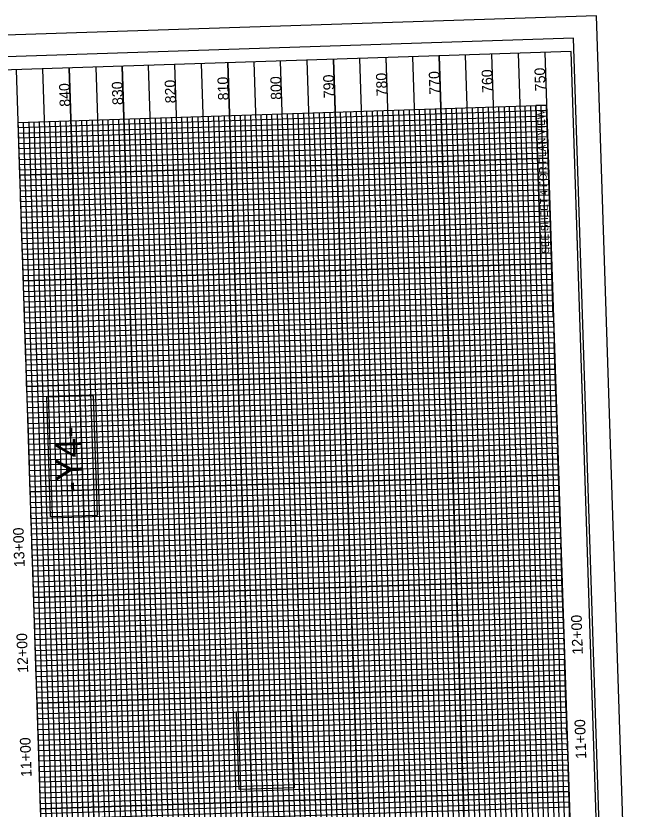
# Model space of a CAD drawing. Extents: x 1627314 to 1628469, y 762309 to 764230.
# Drawn here: x 1627864 to 1628469, y 763293 to 764044 of the extents above; entities that cross this region are included whole.
import ezdxf

# ---------------------------------------------------------------- set-up
doc = ezdxf.new("R2010")
doc.units = 0
for name, color, linetype in [('Exist Vertical Profile Horizontal Axis Label Major', 7, 'Continuous'), ('Exist Vertical Profile Vertical Axis Label', 7, 'Continuous'), ('Prop DSN Text', 7, 'Continuous'), ('Prop Grid Mask', 7, 'Continuous'), ('Sheet Data Field CELL', 7, 'Continuous'), ('Sheet DOT Grid CELL', 7, 'Continuous'), ('Sheet Layout Profile Border Port 2', 7, 'Continuous'), ('Sheet Plot Border Inside CELL', 7, 'Continuous'), ('Sheet Plot Border Outside CELL', 7, 'Continuous'), ('Sheet Profile CELL', 7, 'Continuous'), ('Sheet Profile Grid Major CELL', 7, 'Continuous'), ('Sheet Profile Grid Middle CELL', 7, 'Continuous'), ('Sheet Profile Grid Minor CELL', 7, 'Continuous')]:
    doc.layers.add(name, color=color, linetype=linetype)

msp = doc.modelspace()

# ---------------------------------------------------------------- linework, layer by layer
at = {"layer": 'Prop Grid Mask'}
for points in [[(1628356.37, 763959.45), (1628361.12, 763814.53), (1628371.11, 763814.85), (1628366.37, 763959.78)], [(1627941.73, 763571.76), (1627938.03, 763684.79), (1627893.31, 763683.33), (1627897.01, 763570.3)], [(1628075.63, 763311.97), (1628073.23, 763385.36), (1628125.26, 763387.06), (1628127.66, 763313.68)]]:
    msp.add_lwpolyline(points, close=True, dxfattribs=at)
at = {"layer": 'Sheet DOT Grid CELL'}
for p, q in [((1628313.83, 762507.28), (1628264.79, 764006.37)), ((1628363.8, 762508.92), (1628314.77, 764008)), ((1628063.96, 762499.11), (1628014.93, 763998.19)), ((1628113.93, 762500.74), (1628064.9, 763999.83)), ((1628163.91, 762502.38), (1628114.87, 764001.46)), ((1628213.88, 762504.01), (1628164.85, 764003.1)), ((1628263.85, 762505.65), (1628214.82, 764004.73)), ((1627914.04, 762494.2), (1627865.01, 763993.29)), ((1627964.01, 762495.84), (1627914.98, 763994.92)), ((1628013.99, 762497.47), (1627964.95, 763996.56)), ((1627866.64, 763943.43), (1628366.37, 763959.78)), ((1627868.27, 763893.46), (1628368, 763909.8)), ((1627869.91, 763843.48), (1628369.64, 763859.83)), ((1627871.54, 763793.51), (1628371.27, 763809.86)), ((1627873.18, 763743.54), (1628372.91, 763759.88)), ((1627874.81, 763693.56), (1628374.54, 763709.91)), ((1627876.44, 763643.59), (1628376.18, 763659.94)), ((1627878.08, 763593.62), (1628377.81, 763609.96)), ((1627879.71, 763543.64), (1628379.45, 763559.99)), ((1627881.35, 763493.67), (1628381.08, 763510.02)), ((1627882.98, 763443.7), (1628382.72, 763460.04)), ((1627884.62, 763393.72), (1628384.35, 763410.07)), ((1627886.25, 763343.75), (1628385.99, 763360.1)), ((1627887.89, 763293.78), (1628387.62, 763310.12))]:
    msp.add_line(p, q, dxfattribs=at)
at = {"layer": 'Sheet Layout Profile Border Port 2'}
msp.add_lwpolyline([(1627912.41, 762544.18), (1627866.64, 763943.43), (1628366.37, 763959.78), (1628412.14, 762560.52)], close=True, dxfattribs=at)
at = {"layer": 'Sheet Plot Border Inside CELL'}
msp.add_lwpolyline([(1628446.34, 762357.53), (1628391.86, 764023.14), (1627337.33, 763988.65), (1627391.81, 762323.04)], close=True, dxfattribs=at)
at = {"layer": 'Sheet Plot Border Outside CELL'}
msp.add_lwpolyline([(1628469.21, 762345.27), (1628413.63, 764044.37), (1627314.22, 764008.4), (1627369.79, 762309.31)], close=True, dxfattribs=at)
at = {"layer": 'Sheet Profile CELL'}
for p, q in [((1628364.74, 764009.75), (1628413.77, 762510.55)), ((1628438.76, 762511.37), (1628389.72, 764010.57)), ((1627914.04, 762494.2), (1627865, 763993.4))]:
    msp.add_line(p, q, dxfattribs=at)
msp.add_lwpolyline([(1627340.28, 763976.24), (1627389.32, 762477.04), (1628438.76, 762511.37), (1628389.72, 764010.57)], close=True, dxfattribs=at)
at = {"layer": 'Sheet Profile Grid Major CELL'}
for p, q in [((1627868.27, 763893.46), (1627866.64, 763943.43)), ((1628368, 763909.8), (1628368, 763909.8)), ((1627871.54, 763793.51), (1627869.91, 763843.48)), ((1627874.81, 763693.56), (1627873.18, 763743.54)), ((1627878.08, 763593.62), (1627876.44, 763643.59)), ((1627881.35, 763493.67), (1627879.71, 763543.64)), ((1627884.62, 763393.72), (1627882.98, 763443.7)), ((1627887.89, 763293.78), (1627886.25, 763343.75))]:
    msp.add_line(p, q, dxfattribs=at)
for points in [[(1628264.79, 764006.48), (1628313.83, 762507.28), (1628313.83, 762507.28), (1628363.8, 762508.92), (1628314.76, 764008.11)], [(1628364.74, 764009.75), (1628413.77, 762510.55)], [(1627964.95, 763996.67), (1628013.99, 762497.47), (1628063.96, 762499.11), (1628014.92, 763998.31)], [(1628064.9, 763999.94), (1628113.93, 762500.74), (1628163.91, 762502.38), (1628114.87, 764001.58)], [(1628164.84, 764003.21), (1628213.88, 762504.01), (1628263.85, 762505.65), (1628214.82, 764004.85)], [(1627914.98, 763995.04), (1627964.01, 762495.84)], [(1628389.25, 763260.15), (1628387.62, 763310.12), (1627887.89, 763293.78), (1627886.25, 763343.75), (1628385.99, 763360.1), (1628384.35, 763410.07), (1627884.62, 763393.72), (1627882.98, 763443.7), (1628382.72, 763460.04), (1628381.08, 763510.02), (1627881.35, 763493.67), (1627879.71, 763543.64), (1628379.45, 763559.99), (1628377.81, 763609.96), (1627878.08, 763593.62), (1627876.44, 763643.59), (1628376.18, 763659.94), (1628374.54, 763709.91), (1627874.81, 763693.56), (1627873.18, 763743.54), (1628372.91, 763759.88), (1628371.27, 763809.86), (1627871.54, 763793.51), (1627869.91, 763843.48), (1628369.64, 763859.83), (1628368, 763909.8), (1628368, 763909.8), (1627868.27, 763893.46), (1627866.64, 763943.43), (1628366.37, 763959.78)]]:
    msp.add_lwpolyline(points, dxfattribs=at)
at = {"layer": 'Sheet Profile Grid Middle CELL'}
for points in [[(1628239.8, 764005.66), (1628288.84, 762506.46), (1628338.81, 762508.1), (1628289.78, 764007.3)], [(1628339.75, 764008.93), (1628388.79, 762509.73)], [(1627939.96, 763995.85), (1627989, 762496.66), (1628038.97, 762498.29), (1627989.94, 763997.49)], [(1628039.91, 763999.12), (1628088.95, 762499.93), (1628138.92, 762501.56), (1628089.88, 764000.76)], [(1628139.86, 764002.39), (1628188.89, 762503.2), (1628238.87, 762504.83), (1628189.83, 764004.03)], [(1627939.03, 762495.02), (1627889.99, 763994.22)], [(1628388.44, 763285.14), (1628386.8, 763335.11), (1627887.07, 763318.76), (1627885.44, 763368.74), (1628385.17, 763385.08), (1628383.53, 763435.06), (1627883.8, 763418.71), (1627882.17, 763468.68), (1628381.9, 763485.03), (1628380.26, 763535), (1627880.53, 763518.66), (1627878.9, 763568.63), (1628378.63, 763584.98), (1628376.99, 763634.95), (1627877.26, 763618.6), (1627875.63, 763668.58), (1628375.36, 763684.92), (1628373.73, 763734.9), (1627873.99, 763718.55), (1627872.36, 763768.52), (1628372.09, 763784.87), (1628370.46, 763834.84), (1627870.72, 763818.5), (1627869.09, 763868.47), (1628368.82, 763884.82), (1628367.19, 763934.79), (1627867.45, 763918.44)]]:
    msp.add_lwpolyline(points, dxfattribs=at)
at = {"layer": 'Sheet Profile Grid Minor CELL'}
for p, q in [((1628192.26, 762553.33), (1628146.49, 763952.58)), ((1628151.48, 763952.75), (1628197.25, 762553.5)), ((1628202.25, 762553.66), (1628156.48, 763952.91)), ((1628161.48, 763953.07), (1628207.25, 762553.82)), ((1628217.24, 762554.15), (1628171.47, 763953.4)), ((1628176.47, 763953.56), (1628222.24, 762554.31)), ((1628227.24, 762554.48), (1628181.47, 763953.73)), ((1628186.47, 763953.89), (1628232.24, 762554.64)), ((1628242.23, 762554.97), (1628196.46, 763954.22)), ((1628201.46, 763954.38), (1628247.23, 762555.13)), ((1628252.22, 762555.29), (1628206.46, 763954.55)), ((1628211.45, 763954.71), (1628257.22, 762555.46)), ((1628267.22, 762555.78), (1628221.45, 763955.04)), ((1628226.44, 763955.2), (1628272.21, 762555.95)), ((1628277.21, 762556.11), (1628231.44, 763955.36)), ((1628236.44, 763955.53), (1628282.21, 762556.27)), ((1628292.2, 762556.6), (1628246.43, 763955.85)), ((1628251.43, 763956.02), (1628297.2, 762556.76)), ((1628302.2, 762556.93), (1628256.43, 763956.18)), ((1628261.43, 763956.34), (1628307.2, 762557.09)), ((1628317.19, 762557.42), (1628271.42, 763956.67)), ((1628276.42, 763956.83), (1628322.19, 762557.58)), ((1628327.18, 762557.75), (1628281.42, 763957)), ((1628286.41, 763957.16), (1628332.18, 762557.91)), ((1628342.18, 762558.24), (1628296.41, 763957.49)), ((1628301.4, 763957.65), (1628347.17, 762558.4)), ((1628352.17, 762558.56), (1628306.4, 763957.81)), ((1628311.4, 763957.98), (1628357.17, 762558.73)), ((1628367.16, 762559.05), (1628321.39, 763958.3)), ((1628326.39, 763958.47), (1628372.16, 762559.22)), ((1628377.16, 762559.38), (1628331.39, 763958.63)), ((1628336.39, 763958.8), (1628382.16, 762559.54)), ((1628392.15, 762559.87), (1628346.38, 763959.12)), ((1628351.38, 763959.29), (1628397.15, 762560.03)), ((1628402.14, 762560.2), (1628356.37, 763959.45)), ((1628361.37, 763959.61), (1628361.37, 763959.61)), ((1628407.14, 762560.36), (1628361.37, 763959.61)), ((1627911.61, 763944.9), (1627957.38, 762545.65)), ((1627967.38, 762545.98), (1627921.61, 763945.23)), ((1627926.6, 763945.39), (1627972.37, 762546.14)), ((1627977.37, 762546.3), (1627931.6, 763945.55)), ((1627936.6, 763945.72), (1627982.37, 762546.47)), ((1627992.36, 762546.79), (1627946.59, 763946.05)), ((1627951.59, 763946.21), (1627997.36, 762546.96)), ((1628002.36, 762547.12), (1627956.59, 763946.37)), ((1627961.59, 763946.54), (1628007.36, 762547.28)), ((1628017.35, 762547.61), (1627971.58, 763946.86)), ((1627976.58, 763947.03), (1628022.35, 762547.77)), ((1628027.34, 762547.94), (1627981.58, 763947.19)), ((1627986.57, 763947.35), (1628032.34, 762548.1)), ((1628042.34, 762548.43), (1627996.57, 763947.68)), ((1628001.56, 763947.84), (1628047.33, 762548.59)), ((1628052.33, 762548.75), (1628006.56, 763948.01)), ((1628011.56, 763948.17), (1628057.33, 762548.92)), ((1628067.32, 762549.25), (1628021.55, 763948.5)), ((1628026.55, 763948.66), (1628072.32, 762549.41)), ((1628077.32, 762549.57), (1628031.55, 763948.82)), ((1628036.55, 763948.99), (1628082.32, 762549.74)), ((1628092.31, 762550.06), (1628046.54, 763949.31)), ((1628051.54, 763949.48), (1628097.31, 762550.23)), ((1628102.3, 762550.39), (1628056.54, 763949.64)), ((1628061.53, 763949.8), (1628107.15, 762550.55)), ((1628117.3, 762550.88), (1628071.53, 763950.13)), ((1628076.52, 763950.3), (1628122.29, 762551.04)), ((1628127.29, 762551.21), (1628081.52, 763950.46)), ((1628086.52, 763950.62), (1628132.29, 762551.37)), ((1628142.28, 762551.7), (1628096.51, 763950.95)), ((1628101.51, 763951.11), (1628147.28, 762551.86)), ((1628152.28, 762552.02), (1628106.51, 763951.28)), ((1628111.51, 763951.44), (1628157.28, 762552.19)), ((1628167.27, 762552.51), (1628121.5, 763951.77)), ((1628126.5, 763951.93), (1628172.27, 762552.68)), ((1628177.26, 762552.84), (1628131.5, 763952.09)), ((1628136.49, 763952.26), (1628182.26, 762553)), ((1627917.4, 762544.34), (1627871.63, 763943.59)), ((1627876.63, 763943.76), (1627922.4, 762544.5)), ((1627927.4, 762544.67), (1627881.63, 763943.92)), ((1627886.63, 763944.08), (1627932.4, 762544.83)), ((1627942.39, 762545.16), (1627896.62, 763944.41)), ((1627901.62, 763944.57), (1627947.39, 762545.32)), ((1627952.38, 762545.49), (1627906.62, 763944.74))]:
    msp.add_line(p, q, dxfattribs=at)
for points in [[(1628374.87, 763699.91), (1628374.71, 763704.91), (1627874.97, 763688.57), (1627874.65, 763698.56), (1628374.38, 763714.91), (1628374.22, 763719.9), (1627874.48, 763703.56), (1627874.32, 763708.56), (1628374.05, 763724.9), (1628373.89, 763729.9), (1627874.16, 763713.55), (1627873.83, 763723.55), (1628373.56, 763739.89), (1628373.4, 763744.89), (1627873.67, 763728.54), (1627873.5, 763733.54), (1628373.24, 763749.89), (1628373.07, 763754.89), (1627873.34, 763738.54), (1627873.01, 763748.53), (1628372.74, 763764.88), (1628372.58, 763769.88), (1627872.85, 763753.53), (1627872.68, 763758.53), (1628372.42, 763774.87), (1628372.25, 763779.87), (1627872.52, 763763.53), (1627872.19, 763773.52), (1628371.93, 763789.87), (1628371.76, 763794.86), (1627872.03, 763778.52), (1627871.87, 763783.52), (1628371.6, 763799.86), (1628371.44, 763804.86), (1627871.7, 763788.51), (1627871.38, 763798.51), (1628371.11, 763814.85), (1628370.95, 763819.85), (1627871.21, 763803.5), (1627871.05, 763808.5), (1628370.78, 763824.85), (1628370.62, 763829.85), (1627870.89, 763813.5), (1627870.56, 763823.49), (1628370.29, 763839.84), (1628370.13, 763844.84), (1627870.4, 763828.49), (1627870.23, 763833.49), (1628369.97, 763849.83), (1628369.8, 763854.83), (1627870.07, 763838.49), (1627869.74, 763848.48), (1628369.48, 763864.83), (1628369.31, 763869.82), (1627869.58, 763853.48), (1627869.42, 763858.48), (1628369.15, 763874.82), (1628368.99, 763879.82), (1627869.25, 763863.47), (1627868.93, 763873.47), (1628368.66, 763889.81), (1628368.49, 763894.81), (1627868.76, 763878.46), (1627868.6, 763883.46), (1628368.33, 763899.81), (1628368.17, 763904.81), (1627868.43, 763888.46), (1627868.11, 763898.45), (1628367.84, 763914.8), (1628367.68, 763919.8), (1627867.94, 763903.45), (1627867.78, 763908.45), (1628367.51, 763924.79), (1628367.35, 763929.79), (1627867.62, 763913.45), (1627867.29, 763923.44), (1628367.02, 763939.79), (1628366.86, 763944.78), (1627867.13, 763928.44), (1627866.96, 763933.44), (1628366.7, 763949.78), (1628366.53, 763954.78), (1627866.8, 763938.43), (1627866.64, 763943.43)], [(1628384.84, 763395.08), (1627885.11, 763378.73), (1627884.94, 763383.73), (1628384.68, 763400.08), (1628384.51, 763405.07), (1627884.78, 763388.73), (1627884.45, 763398.72), (1628384.19, 763415.07), (1628384.02, 763420.06), (1627884.29, 763403.72), (1627884.13, 763408.72), (1628383.86, 763425.06), (1628383.7, 763430.06), (1627883.96, 763413.71), (1627883.64, 763423.71), (1628383.37, 763440.05), (1628383.21, 763445.05), (1627883.47, 763428.7), (1627883.31, 763433.7), (1628383.04, 763450.05), (1628382.88, 763455.05), (1627883.15, 763438.7), (1627882.82, 763448.69), (1628382.55, 763465.04), (1628382.39, 763470.04), (1627882.66, 763453.69), (1627882.49, 763458.69), (1628382.23, 763475.04), (1628382.06, 763480.03), (1627882.33, 763463.69), (1627882, 763473.68), (1628381.74, 763490.03), (1628381.57, 763495.02), (1627881.84, 763478.68), (1627881.68, 763483.68), (1628381.41, 763500.02), (1628381.24, 763505.02), (1627881.51, 763488.67), (1627881.19, 763498.67), (1628380.92, 763515.01), (1628380.75, 763520.01), (1627881.02, 763503.66), (1627880.86, 763508.66), (1628380.59, 763525.01), (1628380.43, 763530.01), (1627880.69, 763513.66), (1627880.37, 763523.65), (1628380.1, 763540), (1628379.94, 763545), (1627880.2, 763528.65), (1627880.04, 763533.65), (1628379.77, 763550), (1628379.61, 763554.99), (1627879.88, 763538.65), (1627879.55, 763548.64), (1628379.28, 763564.99), (1628379.12, 763569.98), (1627879.39, 763553.64), (1627879.22, 763558.64), (1628378.96, 763574.98), (1628378.79, 763579.98), (1627879.06, 763563.63), (1627878.73, 763573.63), (1628378.47, 763589.97), (1628378.3, 763594.97), (1627878.57, 763578.62), (1627878.41, 763583.62), (1628378.14, 763599.97), (1628377.98, 763604.97), (1627878.24, 763588.62), (1627877.92, 763598.61), (1628377.65, 763614.96), (1628377.49, 763619.96), (1627877.75, 763603.61), (1627877.59, 763608.61), (1628377.32, 763624.95), (1628377.16, 763629.95), (1627877.43, 763613.61), (1627877.1, 763623.6), (1628376.83, 763639.95), (1628376.67, 763644.94), (1627876.93, 763628.6), (1627876.77, 763633.6), (1628376.5, 763649.94), (1628376.34, 763654.94), (1627876.61, 763638.59), (1627876.28, 763648.59), (1628376.01, 763664.93), (1628375.85, 763669.93), (1627876.12, 763653.58), (1627875.95, 763658.58), (1628375.69, 763674.93), (1628375.52, 763679.93), (1627875.79, 763663.58), (1627875.46, 763673.57), (1628375.2, 763689.92), (1628375.03, 763694.92), (1627875.3, 763678.57), (1627875.14, 763683.57), (1628374.87, 763699.91)], [(1627888.21, 763283.78), (1628387.95, 763300.13), (1628387.78, 763305.13), (1627888.05, 763288.78), (1627887.72, 763298.77), (1628387.46, 763315.12), (1628387.29, 763320.12), (1627887.56, 763303.77), (1627887.4, 763308.77), (1628387.13, 763325.12), (1628386.97, 763330.11), (1627887.23, 763313.77), (1627886.91, 763323.76), (1628386.64, 763340.11), (1628386.48, 763345.1), (1627886.74, 763328.76), (1627886.58, 763333.76), (1628386.31, 763350.1), (1628386.15, 763355.1), (1627886.42, 763338.75), (1627886.09, 763348.75), (1628385.82, 763365.09), (1628385.12, 763369.77), (1628385.66, 763370.09), (1627885.93, 763353.75), (1627885.76, 763358.74), (1628385.49, 763375.09), (1628385.33, 763380.09), (1627885.6, 763363.74), (1627885.27, 763373.73), (1628385, 763390.08), (1628384.84, 763395.08)], [(1628388.27, 763290.13), (1628388.11, 763295.13), (1627888.38, 763278.79)]]:
    msp.add_lwpolyline(points, dxfattribs=at)

# ---------------------------------------------------------------- texts
at = {"layer": 'Exist Vertical Profile Horizontal Axis Label Major'}
for s, p in [('13+00', (1627872.9, 763522.58)), ('12+00', (1628400.88, 763439.94)), ('12+00', (1627876.17, 763422.63)), ('11+00', (1628404.12, 763341.07)), ('11+00', (1627879.4, 763323.91))]:
    msp.add_text(s, height=10, rotation=91.87347, dxfattribs=at).set_placement(p)
at = {"layer": 'Exist Vertical Profile Vertical Axis Label'}
for s, p in [('780', (1628215.76, 763968.29)), ('770', (1628265.73, 763969.92)), ('760', (1628315.71, 763971.56)), ('750', (1628365.68, 763973.19)), ('820', (1628015.87, 763961.75)), ('810', (1628065.8, 763964.58)), ('800', (1628115.81, 763965.02)), ('790', (1628165.79, 763966.65)), ('840', (1627915.92, 763958.48)), ('830', (1627965.89, 763960.12))]:
    msp.add_text(s, height=10, rotation=91.87347, dxfattribs=at).set_placement(p)
at = {"layer": 'Prop DSN Text'}
msp.add_text('SEE SHEET 4 FOR PLAN VIEW', height=7, rotation=91.87347, dxfattribs=at).set_placement((1628369.01, 763819.37))
at = {"layer": 'Sheet Data Field CELL'}
msp.add_text('-Y4-', height=25, rotation=91.87347, dxfattribs=at).set_placement((1627927.97, 763593.05))

doc.saveas('drawing.dxf')
